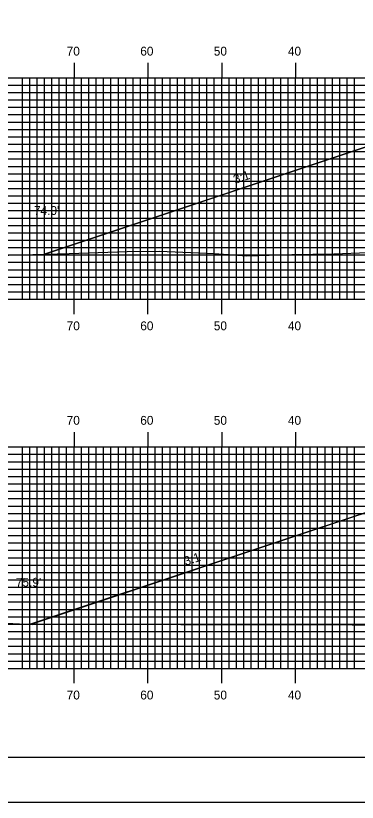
# Model space of a CAD drawing. Extents: x 1762184 to 1762528, y 442591 to 442811.
# Drawn here: x 1762272.4 to 1762318.6, y 442590.5 to 442697.1 of the extents above; entities that cross this region are included whole.
import ezdxf

# ---------------------------------------------------------------- set-up
doc = ezdxf.new("R2010")
doc.units = 0
for name, color, linetype in [('ANNOTATION', 7, 'Continuous'), ('BORDER', 7, 'Continuous'), ('D_Roadway_Centerline', 7, 'Continuous'), ('D_Roadway_SlopeLines', 7, 'Continuous'), ('D_Text_Standard', 7, 'Continuous'), ('H_V ANNOTATION', 7, 'Continuous'), ('MAJOR', 7, 'Continuous'), ('MINOR', 7, 'Continuous'), ('PLOT BOUNDARY', 7, 'Continuous'), ('S_Roadway_Centerline', 7, 'Continuous')]:
    doc.layers.add(name, color=color, linetype=linetype)

msp = doc.modelspace()

# ---------------------------------------------------------------- linework, layer by layer
at = {"layer": 'BORDER'}
msp.add_lwpolyline([(1762200.67, 442596.67), (1762520.67, 442596.67), (1762520.67, 442806.67), (1762200.67, 442806.67)], close=True, dxfattribs=at)
at = {"layer": 'D_Roadway_Centerline'}
for points in [[(1762276.26, 442664.78), (1762276.28, 442664.79), (1762319.01, 442679.03), (1762324.63, 442680.9), (1762327.26, 442681.78), (1762327.27, 442681.78), (1762330.27, 442681.9), (1762330.27, 442681.9), (1762335.32, 442682.11), (1762338.27, 442682.22), (1762341.12, 442682.33), (1762350.26, 442682.66), (1762350.27, 442682.66), (1762362.26, 442683.09), (1762362.27, 442683.09), (1762362.27, 442683.09), (1762367.62, 442682.87), (1762376.24, 442682.53), (1762376.25, 442682.53), (1762385.9, 442680.12), (1762385.9, 442680.11), (1762388.25, 442679.53), (1762388.25, 442679.53), (1762428.32, 442666.17)], [(1762274.37, 442614.65), (1762275.12, 442614.9), (1762318.99, 442629.52), (1762319.01, 442629.53), (1762325.19, 442631.59), (1762327.27, 442632.28), (1762330.26, 442632.4), (1762330.27, 442632.4), (1762338.27, 442632.72), (1762338.27, 442632.72), (1762350.26, 442633.16), (1762350.27, 442633.16), (1762362.26, 442633.59), (1762362.27, 442633.59), (1762375.55, 442633.06), (1762376.11, 442633.03), (1762385.78, 442630.62), (1762388.12, 442630.03), (1762388.13, 442630.03), (1762429.23, 442616.33)]]:
    msp.add_lwpolyline(points, dxfattribs=at)
at = {"layer": 'D_Roadway_SlopeLines'}
for points in [[(1762327.27, 442681.78), (1762276.26, 442664.78)], [(1762327.27, 442632.28), (1762274.37, 442614.65)]]:
    msp.add_lwpolyline(points, dxfattribs=at)
at = {"layer": 'MAJOR'}
for p, q in [((1762280.27, 442690.67), (1762280.27, 442688.67)), ((1762290.27, 442690.67), (1762290.27, 442688.67)), ((1762300.27, 442690.67), (1762300.27, 442688.67)), ((1762310.27, 442690.67), (1762310.27, 442688.67)), ((1762210.27, 442688.67), (1762490.27, 442688.67)), ((1762210.27, 442688.67), (1762490.27, 442688.67)), ((1762280.27, 442658.67), (1762280.27, 442688.67)), ((1762290.27, 442658.67), (1762290.27, 442688.67)), ((1762300.27, 442658.67), (1762300.27, 442688.67)), ((1762310.27, 442658.67), (1762310.27, 442688.67)), ((1762210.27, 442683.67), (1762490.27, 442683.67)), ((1762210.27, 442678.67), (1762490.27, 442678.67)), ((1762210.27, 442673.67), (1762490.27, 442673.67)), ((1762210.27, 442668.67), (1762490.27, 442668.67)), ((1762210.27, 442663.67), (1762490.27, 442663.67)), ((1762210.27, 442658.67), (1762490.27, 442658.67)), ((1762210.27, 442658.67), (1762490.27, 442658.67)), ((1762280.27, 442656.66), (1762280.27, 442658.67)), ((1762290.27, 442656.66), (1762290.27, 442658.67)), ((1762300.27, 442656.66), (1762300.27, 442658.67)), ((1762310.27, 442656.66), (1762310.27, 442658.67)), ((1762280.27, 442640.67), (1762280.27, 442638.67)), ((1762290.27, 442640.67), (1762290.27, 442638.67)), ((1762300.27, 442640.67), (1762300.27, 442638.67)), ((1762310.27, 442640.67), (1762310.27, 442638.67)), ((1762210.27, 442638.67), (1762490.27, 442638.67)), ((1762210.27, 442638.67), (1762490.27, 442638.67)), ((1762280.27, 442608.67), (1762280.27, 442638.67)), ((1762290.27, 442608.67), (1762290.27, 442638.67)), ((1762300.27, 442608.67), (1762300.27, 442638.67)), ((1762310.27, 442608.67), (1762310.27, 442638.67)), ((1762210.27, 442633.67), (1762490.27, 442633.67)), ((1762210.27, 442628.67), (1762490.27, 442628.67)), ((1762210.27, 442623.67), (1762490.27, 442623.67)), ((1762210.27, 442618.67), (1762490.27, 442618.67)), ((1762210.27, 442613.67), (1762490.27, 442613.67)), ((1762210.27, 442608.67), (1762490.27, 442608.67)), ((1762210.27, 442608.67), (1762490.27, 442608.67)), ((1762280.27, 442606.66), (1762280.27, 442608.67)), ((1762290.27, 442606.66), (1762290.27, 442608.67)), ((1762300.27, 442606.66), (1762300.27, 442608.67)), ((1762310.27, 442606.66), (1762310.27, 442608.67))]:
    msp.add_line(p, q, dxfattribs=at)
at = {"layer": 'MINOR'}
for p, q in [((1762273.27, 442658.67), (1762273.27, 442688.67)), ((1762274.27, 442658.67), (1762274.27, 442688.67)), ((1762275.27, 442658.67), (1762275.27, 442688.67)), ((1762276.27, 442658.67), (1762276.27, 442688.67)), ((1762277.27, 442658.67), (1762277.27, 442688.67)), ((1762278.27, 442658.67), (1762278.27, 442688.67)), ((1762279.27, 442658.67), (1762279.27, 442688.67)), ((1762281.27, 442658.67), (1762281.27, 442688.67)), ((1762282.27, 442658.67), (1762282.27, 442688.67)), ((1762283.27, 442658.67), (1762283.27, 442688.67)), ((1762284.27, 442658.67), (1762284.27, 442688.67)), ((1762285.27, 442658.67), (1762285.27, 442688.67)), ((1762286.27, 442658.67), (1762286.27, 442688.67)), ((1762287.27, 442658.67), (1762287.27, 442688.67)), ((1762288.27, 442658.67), (1762288.27, 442688.67)), ((1762289.27, 442658.67), (1762289.27, 442688.67)), ((1762291.27, 442658.67), (1762291.27, 442688.67)), ((1762292.27, 442658.67), (1762292.27, 442688.67)), ((1762293.27, 442658.67), (1762293.27, 442688.67)), ((1762294.27, 442658.67), (1762294.27, 442688.67)), ((1762295.27, 442658.67), (1762295.27, 442688.67)), ((1762296.27, 442658.67), (1762296.27, 442688.67)), ((1762297.27, 442658.67), (1762297.27, 442688.67)), ((1762298.27, 442658.67), (1762298.27, 442688.67)), ((1762299.27, 442658.67), (1762299.27, 442688.67)), ((1762301.27, 442658.67), (1762301.27, 442688.67)), ((1762302.27, 442658.67), (1762302.27, 442688.67)), ((1762303.27, 442658.67), (1762303.27, 442688.67)), ((1762304.27, 442658.67), (1762304.27, 442688.67)), ((1762305.27, 442658.67), (1762305.27, 442688.67)), ((1762306.27, 442658.67), (1762306.27, 442688.67)), ((1762307.27, 442658.67), (1762307.27, 442688.67)), ((1762308.27, 442658.67), (1762308.27, 442688.67)), ((1762309.27, 442658.67), (1762309.27, 442688.67)), ((1762311.27, 442658.67), (1762311.27, 442688.67)), ((1762312.27, 442658.67), (1762312.27, 442688.67)), ((1762313.27, 442658.67), (1762313.27, 442688.67)), ((1762314.27, 442658.67), (1762314.27, 442688.67)), ((1762315.27, 442658.67), (1762315.27, 442688.67)), ((1762316.27, 442658.67), (1762316.27, 442688.67)), ((1762317.27, 442658.67), (1762317.27, 442688.67)), ((1762318.27, 442658.67), (1762318.27, 442688.67)), ((1762210.27, 442687.67), (1762490.27, 442687.67)), ((1762210.27, 442686.67), (1762490.27, 442686.67)), ((1762210.27, 442685.67), (1762490.27, 442685.67)), ((1762210.27, 442684.67), (1762490.27, 442684.67)), ((1762210.27, 442682.67), (1762490.27, 442682.67)), ((1762210.27, 442681.67), (1762490.27, 442681.67)), ((1762210.27, 442680.67), (1762490.27, 442680.67)), ((1762210.27, 442679.67), (1762490.27, 442679.67)), ((1762210.27, 442677.67), (1762490.27, 442677.67)), ((1762210.27, 442676.67), (1762490.27, 442676.67)), ((1762210.27, 442675.67), (1762490.27, 442675.67)), ((1762210.27, 442674.67), (1762490.27, 442674.67)), ((1762210.27, 442672.67), (1762490.27, 442672.67)), ((1762210.27, 442671.67), (1762490.27, 442671.67)), ((1762210.27, 442670.67), (1762490.27, 442670.67)), ((1762210.27, 442669.67), (1762490.27, 442669.67)), ((1762210.27, 442667.67), (1762490.27, 442667.67)), ((1762210.27, 442666.67), (1762490.27, 442666.67)), ((1762210.27, 442665.67), (1762490.27, 442665.67)), ((1762210.27, 442664.67), (1762490.27, 442664.67)), ((1762210.27, 442662.67), (1762490.27, 442662.67)), ((1762210.27, 442661.67), (1762490.27, 442661.67)), ((1762210.27, 442660.67), (1762490.27, 442660.67)), ((1762210.27, 442659.67), (1762490.27, 442659.67)), ((1762210.27, 442637.67), (1762490.27, 442637.67)), ((1762273.27, 442608.67), (1762273.27, 442638.67)), ((1762274.27, 442608.67), (1762274.27, 442638.67)), ((1762275.27, 442608.67), (1762275.27, 442638.67)), ((1762276.27, 442608.67), (1762276.27, 442638.67)), ((1762277.27, 442608.67), (1762277.27, 442638.67)), ((1762278.27, 442608.67), (1762278.27, 442638.67)), ((1762279.27, 442608.67), (1762279.27, 442638.67)), ((1762281.27, 442608.67), (1762281.27, 442638.67)), ((1762282.27, 442608.67), (1762282.27, 442638.67)), ((1762283.27, 442608.67), (1762283.27, 442638.67)), ((1762284.27, 442608.67), (1762284.27, 442638.67)), ((1762285.27, 442608.67), (1762285.27, 442638.67)), ((1762286.27, 442608.67), (1762286.27, 442638.67)), ((1762287.27, 442608.67), (1762287.27, 442638.67)), ((1762288.27, 442608.67), (1762288.27, 442638.67)), ((1762289.27, 442608.67), (1762289.27, 442638.67)), ((1762291.27, 442608.67), (1762291.27, 442638.67)), ((1762292.27, 442608.67), (1762292.27, 442638.67)), ((1762293.27, 442608.67), (1762293.27, 442638.67)), ((1762294.27, 442608.67), (1762294.27, 442638.67)), ((1762295.27, 442608.67), (1762295.27, 442638.67)), ((1762296.27, 442608.67), (1762296.27, 442638.67)), ((1762297.27, 442608.67), (1762297.27, 442638.67)), ((1762298.27, 442608.67), (1762298.27, 442638.67)), ((1762299.27, 442608.67), (1762299.27, 442638.67)), ((1762301.27, 442608.67), (1762301.27, 442638.67)), ((1762302.27, 442608.67), (1762302.27, 442638.67)), ((1762303.27, 442608.67), (1762303.27, 442638.67)), ((1762304.27, 442608.67), (1762304.27, 442638.67)), ((1762305.27, 442608.67), (1762305.27, 442638.67)), ((1762306.27, 442608.67), (1762306.27, 442638.67)), ((1762307.27, 442608.67), (1762307.27, 442638.67)), ((1762308.27, 442608.67), (1762308.27, 442638.67)), ((1762309.27, 442608.67), (1762309.27, 442638.67)), ((1762311.27, 442608.67), (1762311.27, 442638.67)), ((1762312.27, 442608.67), (1762312.27, 442638.67)), ((1762313.27, 442608.67), (1762313.27, 442638.67)), ((1762314.27, 442608.67), (1762314.27, 442638.67)), ((1762315.27, 442608.67), (1762315.27, 442638.67)), ((1762316.27, 442608.67), (1762316.27, 442638.67)), ((1762317.27, 442608.67), (1762317.27, 442638.67)), ((1762318.27, 442608.67), (1762318.27, 442638.67)), ((1762210.27, 442636.67), (1762490.27, 442636.67)), ((1762210.27, 442635.67), (1762490.27, 442635.67)), ((1762210.27, 442634.67), (1762490.27, 442634.67)), ((1762210.27, 442632.67), (1762490.27, 442632.67)), ((1762210.27, 442631.67), (1762490.27, 442631.67)), ((1762210.27, 442630.67), (1762490.27, 442630.67)), ((1762210.27, 442629.67), (1762490.27, 442629.67)), ((1762210.27, 442627.67), (1762490.27, 442627.67)), ((1762210.27, 442626.67), (1762490.27, 442626.67)), ((1762210.27, 442625.67), (1762490.27, 442625.67)), ((1762210.27, 442624.67), (1762490.27, 442624.67)), ((1762210.27, 442622.67), (1762490.27, 442622.67)), ((1762210.27, 442621.67), (1762490.27, 442621.67)), ((1762210.27, 442620.67), (1762490.27, 442620.67)), ((1762210.27, 442619.67), (1762490.27, 442619.67)), ((1762210.27, 442617.67), (1762490.27, 442617.67)), ((1762210.27, 442616.67), (1762490.27, 442616.67)), ((1762210.27, 442615.67), (1762490.27, 442615.67)), ((1762210.27, 442614.67), (1762490.27, 442614.67)), ((1762210.27, 442612.67), (1762490.27, 442612.67)), ((1762210.27, 442611.67), (1762490.27, 442611.67)), ((1762210.27, 442610.67), (1762490.27, 442610.67)), ((1762210.27, 442609.67), (1762490.27, 442609.67))]:
    msp.add_line(p, q, dxfattribs=at)
at = {"layer": 'PLOT BOUNDARY'}
msp.add_lwpolyline([(1762184.48, 442590.55), (1762524.48, 442590.55), (1762524.48, 442810.55), (1762184.48, 442810.55)], close=True, dxfattribs=at)
at = {"layer": 'S_Roadway_Centerline'}
for points in [[(1762268.09, 442664.55), (1762279.62, 442664.87), (1762287.46, 442665.12), (1762291.85, 442665.2), (1762299.24, 442664.88), (1762303.67, 442664.54), (1762309.77, 442664.74), (1762315.45, 442664.8), (1762320.1, 442665.01), (1762337.48, 442664.8), (1762340.49, 442664.7), (1762350.84, 442664.88), (1762360.52, 442664.6), (1762362.81, 442664.46), (1762366.93, 442664.52), (1762374.68, 442664.75), (1762379.68, 442664.69), (1762396.12, 442665.22), (1762398.52, 442665.29), (1762399.87, 442665.3), (1762409.23, 442665.41)], [(1762261.27, 442615.28), (1762274.65, 442614.64), (1762284.37, 442614.73), (1762294.75, 442614.6), (1762297.79, 442614.62), (1762313.84, 442614.61), (1762317.95, 442614.56), (1762324.91, 442614.53), (1762330.97, 442614.66), (1762334.91, 442614.72), (1762343.43, 442615), (1762354.32, 442614.87), (1762355.59, 442614.86), (1762356.18, 442614.88), (1762358.44, 442614.88), (1762375.28, 442614.98), (1762378.59, 442615.05), (1762383.24, 442614.86), (1762390.25, 442614.72), (1762395.63, 442614.94), (1762409.26, 442615.5)]]:
    msp.add_lwpolyline(points, dxfattribs=at)

# ---------------------------------------------------------------- texts
at = {"layer": 'ANNOTATION'}
for rotation, p in [(18.44, (1762302.08, 442674.29)), (18.4342, (1762295.39, 442622.57))]:
    msp.add_text('3:1', height=1.2, rotation=rotation, dxfattribs=at).set_placement(p)
at = {"layer": 'D_Text_Standard'}
for s, p in [("74.0'", (1762274.84, 442670.09)), ("75.9'", (1762272.39, 442619.74))]:
    msp.add_text(s, height=1.2, dxfattribs=at).set_placement(p)
at = {"layer": 'H_V ANNOTATION'}
for s, p in [('70', (1762279.27, 442691.67)), ('60', (1762289.24, 442691.67)), ('50', (1762299.2, 442691.67)), ('40', (1762309.24, 442691.67)), ('70', (1762279.27, 442654.47)), ('60', (1762289.24, 442654.47)), ('50', (1762299.2, 442654.47)), ('40', (1762309.24, 442654.47)), ('70', (1762279.27, 442641.67)), ('60', (1762289.24, 442641.67)), ('50', (1762299.2, 442641.67)), ('40', (1762309.24, 442641.67)), ('70', (1762279.27, 442604.47)), ('60', (1762289.24, 442604.47)), ('50', (1762299.2, 442604.47)), ('40', (1762309.24, 442604.47))]:
    msp.add_text(s, height=1.2, dxfattribs=at).set_placement(p)

doc.saveas('drawing.dxf')
